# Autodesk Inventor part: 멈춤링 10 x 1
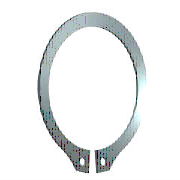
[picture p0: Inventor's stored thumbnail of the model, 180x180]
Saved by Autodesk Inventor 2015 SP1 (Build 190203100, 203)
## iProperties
IsCustomPart: 0
Created: 2009-02
Part Number: 멈춤링 10 x 1
Material: Steel, Mild
Description: 리테이닝 링(C형)
Document SubType Name: Modeling
Standard: KS B 1336
Designer: SeoGD™
Standards Organization: KS
Language: ko-KR
Size Designation: 10 x 1
Categories: <MemberInstance><Categories><Category DisplayName="샤프트 부품" InternalName="7f7aeb1f-a693-4053-b835-cee3144e0d98" Mnemonic="SHFT"><Category DisplayName="써클립" Inter
Density: 7.86 g/cm^3
Appearance: Metal-Steel
Mass: 0.423087 g
Surface Area: 1.9243 cm^2
Volume: 0.0538279 cm^3
Author: SeoGD™
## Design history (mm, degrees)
sketch "스케치1"
  geometry: L1 (-6, 0)-(6, 0) reference; L2 (0, 20.189)-(0, -80.536) reference; L3 (-48.09, 0)-(48.09, 0) reference; L4 (-0.3, -9.791)-(-0.3, -12.791); L5 (-0.3, -6.54)-(-0.3, -13.29); L6 (-2.795, 1.6)-(3.672, 1.6); L7 (0.3, -6.54)-(0.3, -13.29); L8 (0.3, -9.791)-(0.3, -12.791); C1 r 0.6 at (-1.2, -11.486); C2 r 0.6 at (1.2, -11.486); A1 r 4.8 centre (0, -5) between (0.3, -9.791) and (-0.3, -9.791); A2 r 6.2 centre (0, -4.6) between (2.988, -10.033) and (-2.988, -10.033); A3 r 7.796 centre (0, -5) between (-1.418, -12.666) and (-0.3, -12.791); A4 r 1.2 centre (-1.2, -11.486) between (-2.383, -11.285) and (-1.418, -12.666); A5 r 1.2 centre (-3.566, -11.084) between (-2.383, -11.285) and (-2.988, -10.033); A6 r 1.2 centre (3.566, -11.084) between (2.988, -10.033) and (2.383, -11.285); A7 r 1.2 centre (1.2, -11.486) between (1.418, -12.666) and (2.383, -11.285); A8 r 7.796 centre (0, -5) between (0.3, -12.791) and (1.418, -12.666)
  constraints: 16 point on circle, 12 end point, 10 centre point, 9 symmetric about line, 5 point on line, 4 tangent, 3 coincident, 2 horizontal, 1 perpendicular, 1 vertical, 5 other
  dimensions: "d0" = 9.6 diameter of A1 (= ND); "d1" = 3 distance of L4.end L4.start (= SRB2); "d6" = 0.3 distance between parallel lines of L2 L5 (= 0.25 x SD5); "d7" = 1.6 distance between parallel lines of L6 L3 (= SRB1); "d8" = 0.4 distance of A1.centre A2.centre (= 0.25 x SRB1); "d9" = 1.2 radius of A4 (= SD5); "d10" = 1.2 radius of A5 (= SD5); "d11" = 0.9 distance from line of L4 A4.centre (= 0.75 x SD5); "d12" = 1.2 diameter of C1 (= SD5); "d13" = 1.2 diameter of C2 (= SD5); "d14" = 5 distance from line of A1.centre L1 (= 0.5 x WD)
extrude "본체" new body sketch "스케치1" distance "d2" = 1 (= SD); taper "d3" = 0 deg
workaxis "Work Axis1"
workplane "Work Plane1"
body "Solid1"
other parameters: "SD" = 1 [user parameter; used in 1 equation term], "SRB1" = 1.6 [user parameter; used in 2 equation terms], "ND" = 9.6 [user parameter; used in 1 equation term], "SRB2" = 3 [user parameter; used in 1 equation term], "SD5" = 1.2 [user parameter; used in 6 equation terms], "d15" = 0, "d16" = 0, "d17" = 0, "d41" = 0, "d42" = 0, "SD3" = 9.3 [user parameter], "WDMAX" = 11 [user parameter]
